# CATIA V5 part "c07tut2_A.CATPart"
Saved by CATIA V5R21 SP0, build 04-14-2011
Part number: Part1
Bounding box of the stored display mesh (mm): x 0 to 32, y -32 to 32, z -9 to 36
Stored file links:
  D:\CATIA V5R21 E-RESOURCES\CATIA-V5R21\catia-v5r21-prt\c07-catia-v5r20-prt\c07-catia-v5r21-tut-2_A.CATPart
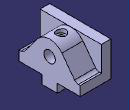
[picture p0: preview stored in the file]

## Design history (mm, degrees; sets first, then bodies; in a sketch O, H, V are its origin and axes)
Body1 (main body)
  Sketch1 on zx-plane, origin (0, 0, 0), H (-1, 0, 0), V (0, 0, 1)
    point P1 (-32, 0)
    line L1 (-32, 0) -> (0, 0)
    line L2 (0, 0) -> (0, 36)
    line L3 (0, 36) -> (-10, 36)
    line L4 (-10, 36) -> (-10, 10)
    line L5 (-10, 10) -> (-32, 10)
    line L6 (-32, 10) -> (-32, 0)
    length L2 = 36
    length L3 = 10
    length L6 = 10
    length L1 = 32
    coincidence: P1 H
    horizontal: L1 H, L3 H, L5 H
    vertical: L2 V, L4 V, L6 V
  Pad1: profile Sketch1, direction (0, 1, 0), length 32, mirrored extent
  Sketch2 on face of Pad1, origin (32, 0, 0), H (0, 1, 0), V (0, 0, 1)
    point P1 (-27.5, 10)
    line L1 (-27.5, 10) -> (-12.8, 29.6)
    arc A1 centre (0, 20) radius 16 from (-12.8, 29.6) to (12.8, 29.6) cw
    point P3 (0, 20)
    line L2 (12.8, 29.6) -> (27.5, 10)
    point P5 (27.5, 10)
    line L3 (27.5, 10) -> (-27.5, 10)
    reference projected line E1 (-32, 10) -> (32, 10) from edge [face of Pad1 | face of Pad1]
    reference projected line E2 (-32, 36) -> (32, 36) from edge [face of Pad1 | face of Pad1]
    length L3 = 55
    radius A1 = 16
    tangency: A1 L1, L2 A1, A1 E2
    horizontal: L3 H
    coincidence: L3 E1, P3 V
    symmetry: P5 P1 V
  Pad2: profile Sketch2, direction (-1, 0, 0), up to the existing solid (limit type 2)
  Sketch3 on face of Pad1, origin (32, 0, 0), H (0, 1, 0), V (0, 0, 1)
    point P1 (-8, 0)
    line L1 (-8, 0) -> (8, 0)
    line L2 (8, 0) -> (8, -9)
    line L3 (8, -9) -> (-8, -9)
    line L4 (-8, -9) -> (-8, 0)
    length L2 = 9
    length L3 = 16
    coincidence: P1 H
    horizontal: L1 H, L3 H
    vertical: L2 V, L4 V
    midpoint: O L1
  Pad3: profile Sketch3, direction (-1, 0, 0), length 32
  Sketch4 on face of Pad1, origin (32, 1.3275, 27.1999), H (0, 1, 0), V (0, 0, 1)
    point P1 (-1.3275, -7.1999)
    reference projected arc E1 centre (-1.3275, -7.1999) radius 16 from (11.4725, 2.4001) to (-14.1275, 2.4001) ccw from edge [face of Pad2 | face of Pad2]
    concentricity: P1 E1
  Hole1: placed by Sketch4, at (32, 0, 20) direction (-1, 0, 0), diameter 12, depth 24
  Sketch5, origin (20, 0, 36), H (1, 0, 0), V (0, 1, 0)
    point P1 (0, 0)
    reference projected point E1 (0, 0) from vertex of Sketch8
    coincidence: E1 P1
  Hole2: placed by Sketch5, at (20, 0, 36) direction (0, 0, -1), diameter 6, depth 16, counterbore diameter 10, counterbore depth 4
  Fillet1: radius 5, on edge [face of Pad1 | face of Pad2]; edge [face of Pad2 | face of Pad1]
  Sketch6 on face of Pad3, origin (17.7485, -3.919, -9), H (1, 0, 0), V (0, -1, 0)
    point P1 (6.2515, -3.919)
    reference projected line E1 (14.2515, 4.081) -> (14.2515, -11.919) from edge [face of Pad3 | face of Pad3]
    reference projected line E2 (14.2515, -35.919) -> (-17.7485, -35.919) from edge [face of Pad1 | face of Pad1]
    distance P1 E1 = 8
    distance E2 P1 = 32
  Hole3: placed by Sketch6, at (24, 0, -9) direction (0, 0, 1), diameter 6, depth 16, V-bottom angle 120
  Sketch7 on face of Pad3, origin (11.2705, -0.1534, -9), H (1, 0, 0), V (0, -1, 0)
    point P1 (-3.2705, -0.1534)
    reference projected line E1 (20.7295, -32.1534) -> (-11.2705, -32.1534) from edge [face of Pad1 | face of Pad1]
    reference projected line E2 (-11.2705, 7.8466) -> (-11.2705, -8.1534) from edge [face of Pad3 | face of Pad3]
    distance P1 E1 = 32
    distance P1 E2 = 8
  Hole4: placed by Sketch7, at (8, 0, -9) direction (0, 0, 1), diameter 6, depth 16, V-bottom angle 120
  Sketch8 on zx-plane, origin (0, 0, 0), H (-1, 0, 0), V (0, 0, 1)
    point P1 (-20, 36)
    reference projected line E1 (0, 36) -> (-10, 36) from edge [face of Pad1 | face of Pad1]
    reference projected line E2 (0, 0) -> (0, 36) from edge [face of Pad1 | face of Pad1]
    distance E2 P1 = 20
    coincidence: P1 E1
